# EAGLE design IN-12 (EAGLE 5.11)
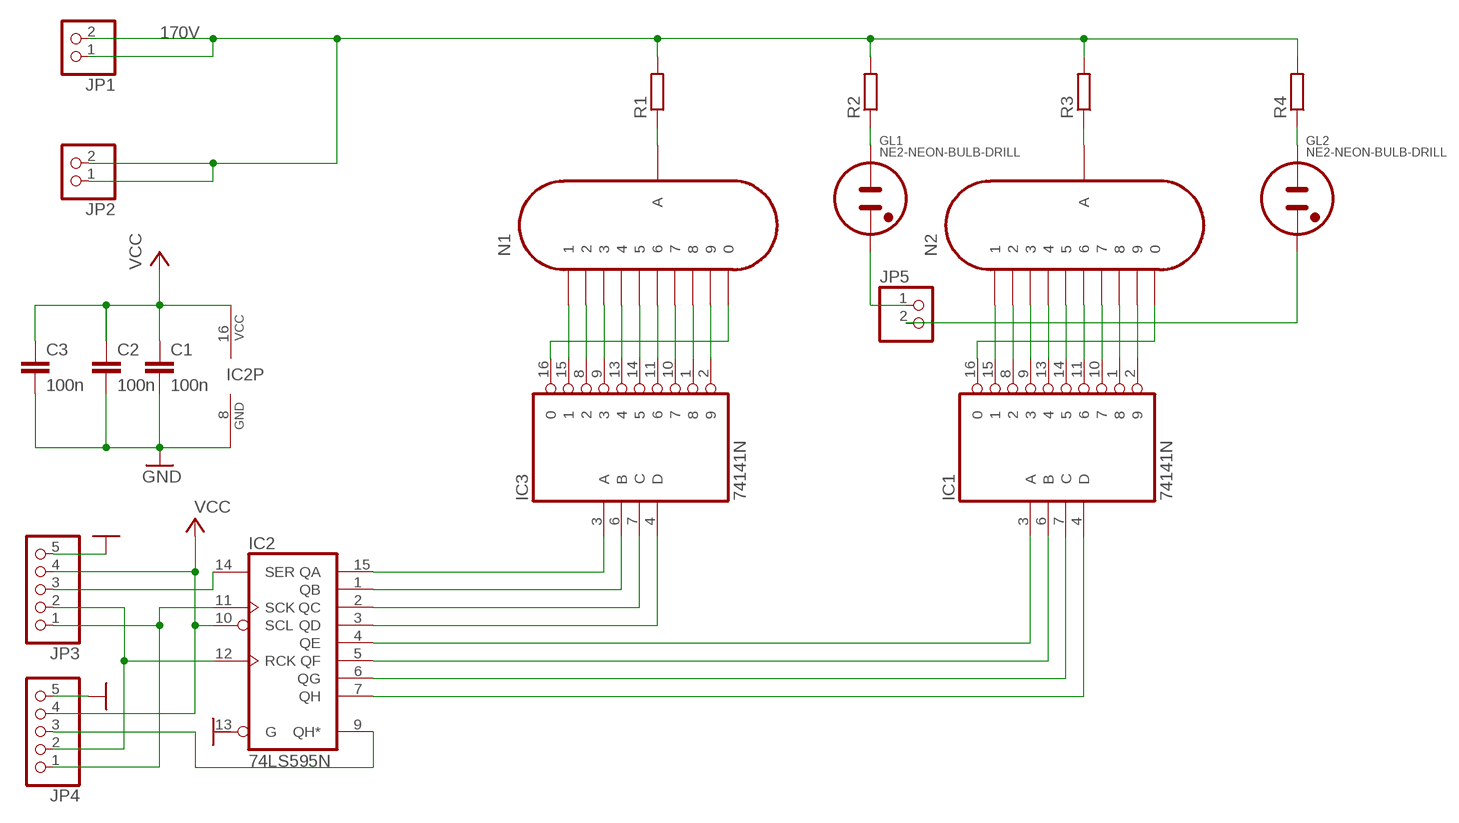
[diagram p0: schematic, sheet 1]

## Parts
C1  100n  C-EU025_050-025X075  [C025_050-025X075]
C2  100n  C-EU025_050-025X075  [C025_050-025X075]
C3  100n  C-EU025_050-025X075  [C025_050-025X075]
GL1  NE2-NEON-BULB-DRILL  [NE2-NEON-BULB-DRILL]
GL2  NE2-NEON-BULB-DRILL  [NE2-NEON-BULB-DRILL]
IC1  74141N  [DIL16]
IC2  74LS595N  [DIL16]
IC3  74141N  [DIL16]
JP1  PINHD-1X2  [1X02]
JP2  PINHD-1X2  [1X02]
JP3  PINHD-1X5  [1X05]
JP4  PINHD-1X5  [1X05]
JP5  PINHD-1X2  [1X02]
N1  IN-12A  [IN-12]
N2  IN-12A  [IN-12]
R1  R-EU_0207/12  [0207/12]
R2  R-EU_0207/12  [0207/12]
R3  R-EU_0207/12  [0207/12]
R4  R-EU_0207/12  [0207/12]

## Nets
170V: JP1.1 JP1.2 JP2.1 JP2.2 R1.2 R2.2 R3.2 R4.2
GND: C1.2 C2.2 C3.2 IC2.8(GND) IC2.13(G) JP3.5 JP4.5
N$1: N1.A R1.1
N$2: N2.A R3.1
N$3: IC1.15 N2.1
N$4: IC1.8 N2.2
N$5: IC1.9 N2.3
N$6: IC1.13 N2.4
N$7: IC1.14 N2.5
N$8: IC1.11 N2.6
N$9: IC1.10 N2.7
N$10: IC1.1 N2.8
N$11: IC1.2 N2.9
N$12: GL1.1(A) R2.1
N$13: IC3.15 N1.1
N$14: IC3.8 N1.2
N$15: IC3.9 N1.3
N$16: IC3.13 N1.4
N$17: IC3.14 N1.5
N$18: IC3.11 N1.6
N$19: IC3.10 N1.7
N$20: IC3.1 N1.8
N$21: IC3.2 N1.9
N$22: IC3.16 N1.0
N$23: IC1.16 N2.0
N$26: GL2.1(A) R4.1
N$27: GL1.2(A1) JP5.1
N$28: IC2.15(QA) IC3.3(A)
N$29: IC2.1(QB) IC3.6(B)
N$30: IC2.2(QC) IC3.7(C)
N$31: IC2.3(QD) IC3.4(D)
N$32: IC1.3(A) IC2.4(QE)
N$33: IC1.6(B) IC2.5(QF)
N$34: IC1.7(C) IC2.6(QG)
N$35: IC1.4(D) IC2.7(QH)
N$37: GL2.2(A1) JP5.2
N$40: IC2.14(SER) JP3.3
N$41: IC2.11(SCK) JP3.1 JP4.1
N$42: IC2.12(RCK) JP3.2 JP4.2
N$45: IC2.9(QH*) JP4.3
VCC: C1.1 C2.1 C3.1 IC2.10(SCL) IC2.16(VCC) JP3.4 JP4.4

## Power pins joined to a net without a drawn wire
GND: IC1.12(GND) IC3.12(GND)
VCC: IC1.5(VCC) IC3.5(VCC)

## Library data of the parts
C1-C3 = resistor:C-EU: CAPACITOR, European symbol
GL1 GL2 = nixies:NE2-NEON-BULB: Neon indicator (wire connection)
IC1 IC3 = 74xx-eu:74*141: BCD to decimal DECODER/DRIVER
IC2 = 74xx-us:74*595: 8-bit SHIFT REGISTER, output latch
JP1 JP2 JP5 = pinhead:PINHD-1X2: PIN HEADER
JP3 JP4 = pinhead:PINHD-1X5: PIN HEADER
N1 N2 = russian-nixies:IN-12A: IN-12A: medium numeric topview nixie tube
R1-R4 = resistor:R-EU_: RESISTOR, European symbol

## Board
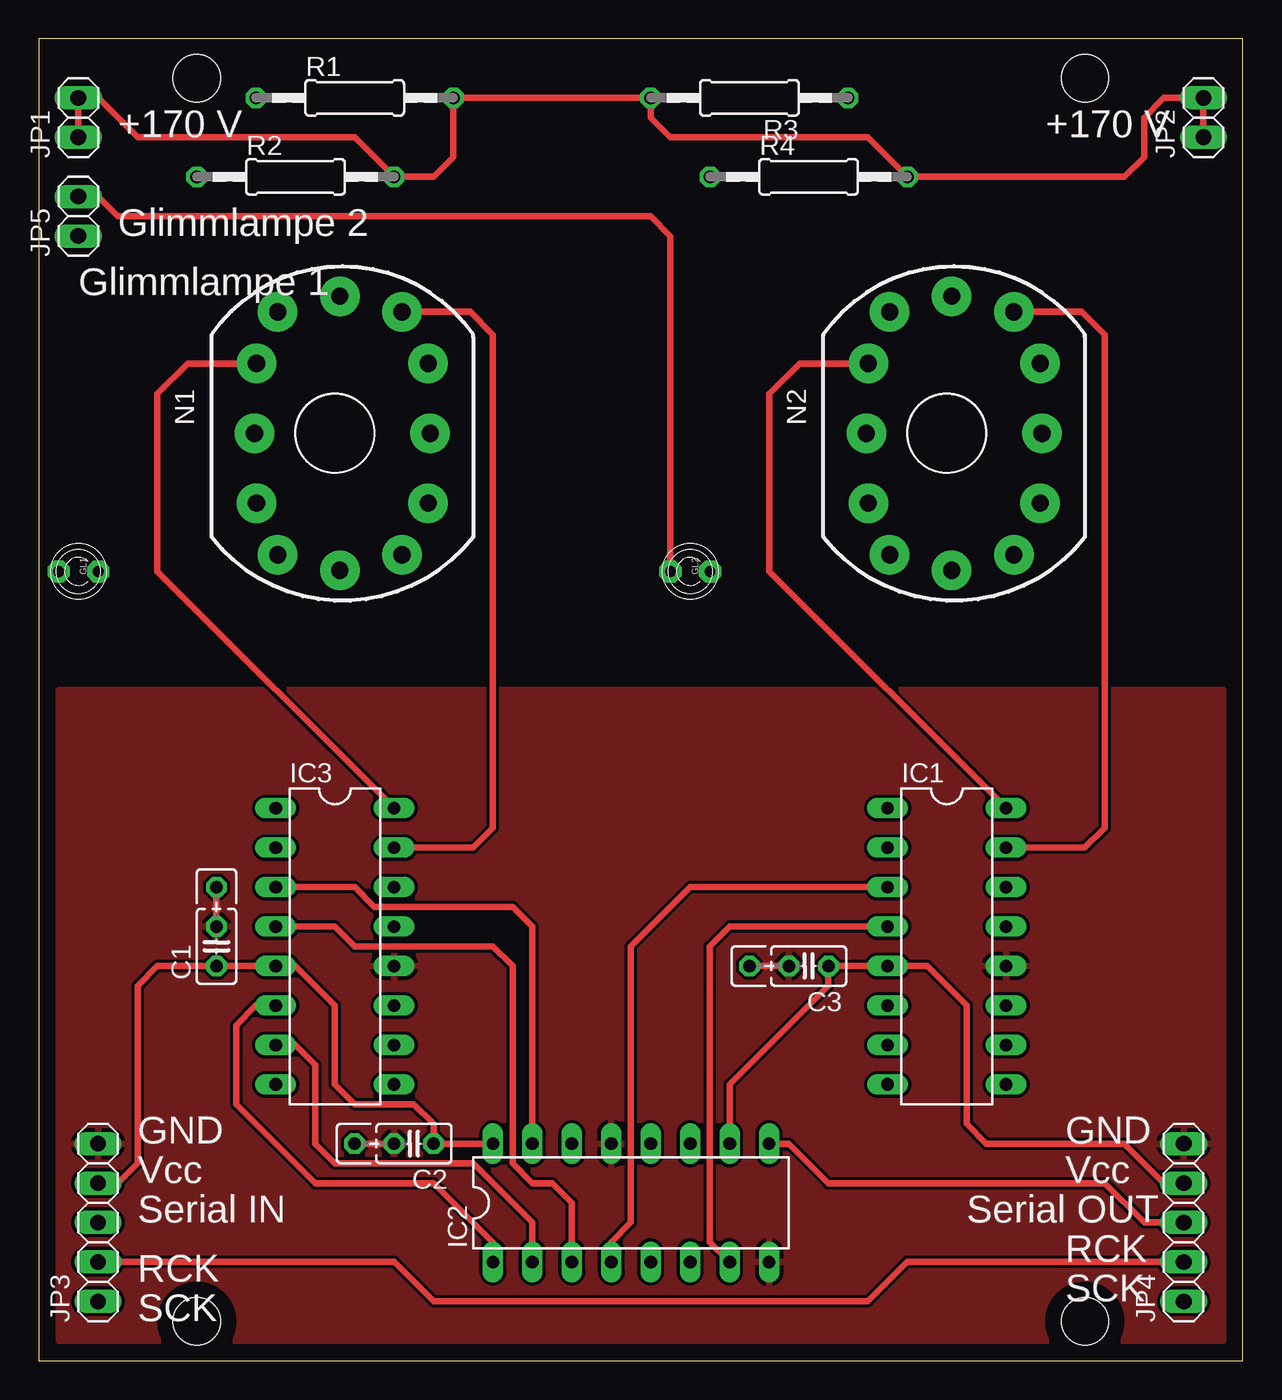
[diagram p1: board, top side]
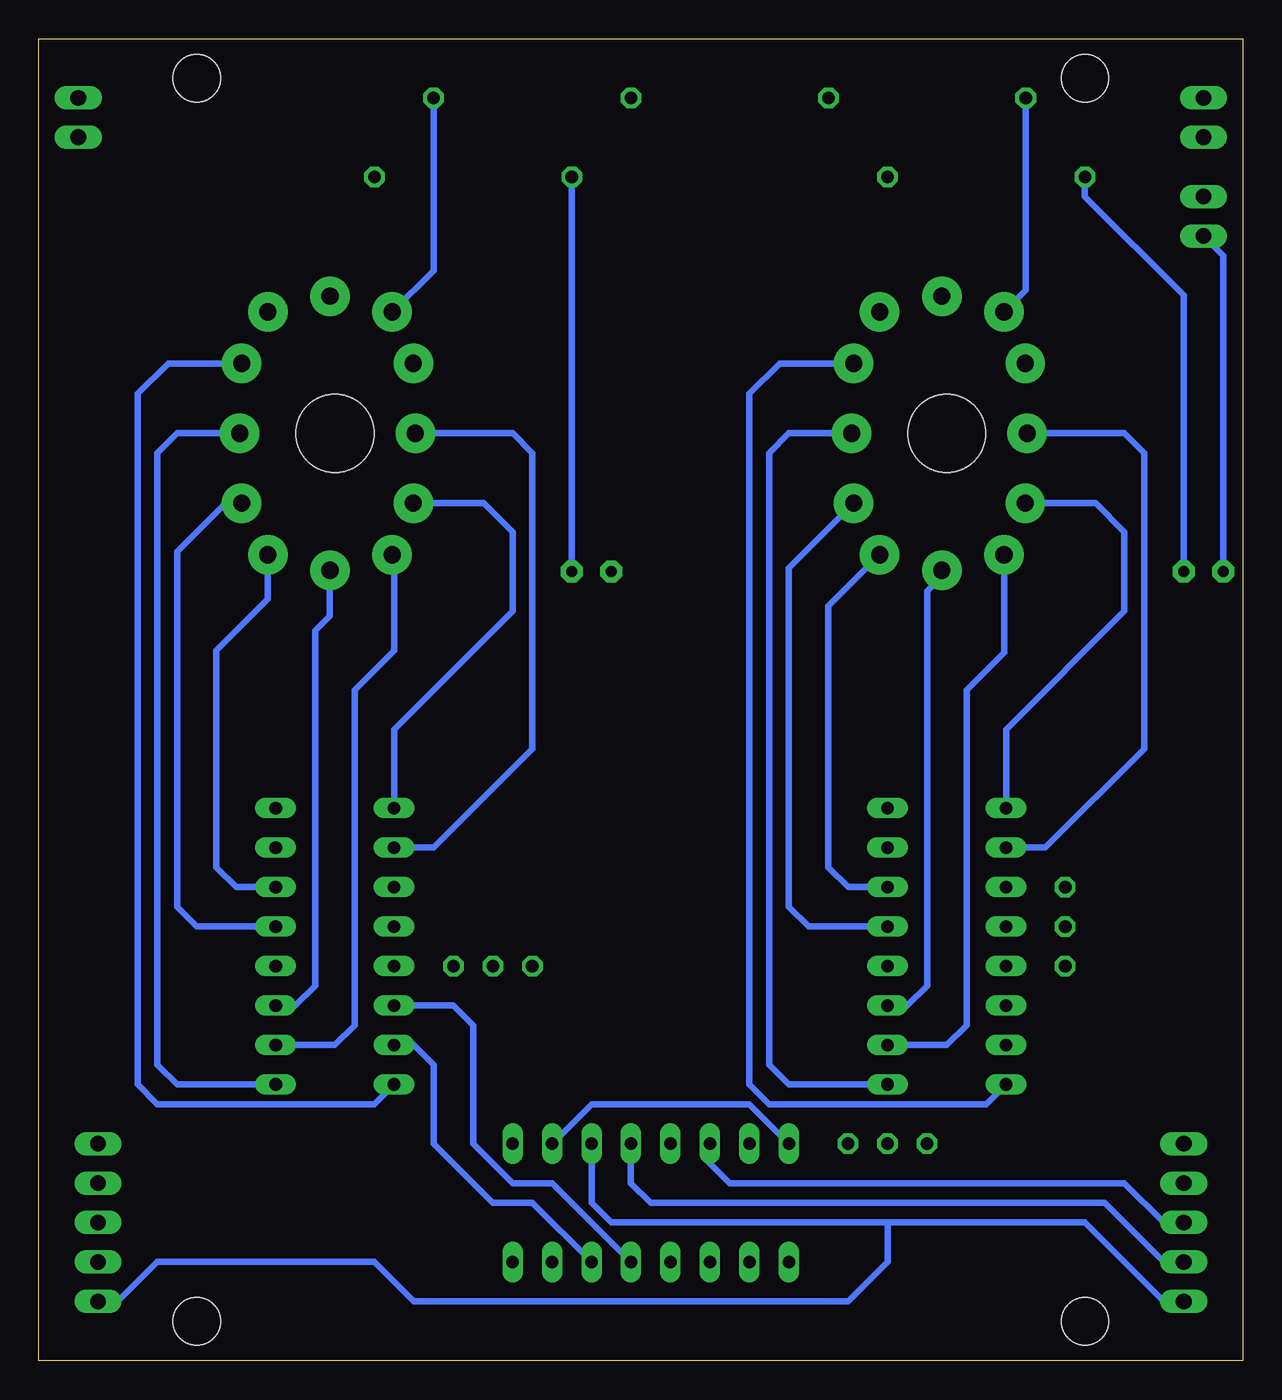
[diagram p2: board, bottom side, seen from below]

Size 77.47 x 85.08 mm. Coordinates in mm from the lower left corner, seen from the top.
Outline: 0,0 77.47,0 77.47,85.08 0,85.08 0,0
Copper layers (1*16): Top 0.035mm / dielectric 1.5mm / Bottom 0.035mm
Design rules "default": minimum track width 10mil, minimum drill 24mil, track to track 8mil, track to pad 8mil, pad to pad 8mil, via to via 8mil, smd to smd 8mil, copper to edge 40mil, drill to drill 8mil, minimum pad ring 10mil, minimum via ring 8mil, stop-mask expansion 4mil, vias tented up to drill 0mil, thermal gap 10mil
Holes 3.05 mm at 10.16,82.55 67.31,82.55 67.31,2.54 10.16,2.54

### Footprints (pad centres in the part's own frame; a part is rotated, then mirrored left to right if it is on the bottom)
C025_050-025X075 = drill 0.813 octagon: 1 -1.27,0; 2 1.27,0; 3 3.81,0
NE2-NEON-BULB-DRILL = drill 0.7 pad 1.422 octagon: 1 0,1.27; 2 0,-1.27
DIL16 = drill 0.813 long: 1 -8.89,-3.81; 2 -6.35,-3.81; 3 -3.81,-3.81; 4 -1.27,-3.81; 5 1.27,-3.81; 6 3.81,-3.81; 7 6.35,-3.81; 8 8.89,-3.81; 9 8.89,3.81; 10 6.35,3.81; 11 3.81,3.81; 12 1.27,3.81; 13 -1.27,3.81; 14 -3.81,3.81; 15 -6.35,3.81; 16 -8.89,3.81
1X02 = drill 1.016 long: 1 -1.27,0; 2 1.27,0
1X05 = drill 1.016 long: 1 -5.08,0; 2 -2.54,0; 3 0,0; 4 2.54,0; 5 5.08,0
IN-12 = drill 1.1 pad 2.54 round: 0 5.048,-4.5; 1 -4.317,-7.817; 2 -6,-4.5; 3 -6.127,0; 4 -6,4.5; 5 -4.317,7.817; 6 -0.318,8.818; 7 3.683,7.817; 8 5.048,4.5; 9 5.175,0; A 3.683,-7.817; LHDP -0.318,-8.818 | hole 5: 0,0
0207/12 = drill 0.813 octagon: 1 -6.35,0; 2 6.35,0

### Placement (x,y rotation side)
C1  11.43,26.67 90 top
C2  24.13,13.97 180 top
C3  49.53,25.4 180 top
GL1  2.54,50.8 270 top
GL2  41.91,50.8 270 top
IC1  58.42,26.67 270 top
IC2  38.1,10.16 0 top
IC3  19.05,26.67 270 top
JP1  2.54,80.01 90 top
JP2  74.93,80.01 90 top
JP3  3.81,8.89 90 top
JP4  73.66,8.89 90 top
JP5  2.54,73.66 90 top
N1  19.05,59.69 180 top
N2  58.42,59.69 180 top
R1  20.32,81.28 0 top
R2  16.51,76.2 0 top
R3  45.72,81.28 180 top
R4  49.53,76.2 0 top

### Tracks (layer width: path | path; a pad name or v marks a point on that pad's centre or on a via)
170V
  Top 0.406: JP1.1 JP1.2 3.81,81.28 6.35,78.74 20.32,78.74 R2.2 25.4,76.2 26.67,77.47 R1.2 R3.2 39.37,80.01 40.64,78.74 53.34,78.74 R4.2 69.85,76.2 71.12,77.47 71.12,80.01 72.39,81.28 JP2.2 JP2.1
GND
  Top 0.406: 20.32,13.97 C2.2 | 45.72,25.4 C3.2 | C1.2 11.43,30.48
  pour Top: 1.27,43.18 76.2,43.18 76.2,1.27 1.27,1.27
N$1
  Bottom 0.406: R1.1 13.97,68.91 N1.A
N$2
  Bottom 0.406: R3.1 52.07,70.17 N2.A
N$3
  Top 0.406: N2.1 67.11,67.51 68.58,66.04 68.58,34.29 67.31,33.02 IC1.15
N$4
  Bottom 0.406: N2.2 69.16,64.19 71.12,62.23 71.12,17.78 69.85,16.51 55.88,16.51 IC1.8
N$5
  Bottom 0.406: N2.3 68.58,59.69 69.85,58.42 69.85,19.05 68.58,17.78 IC1.9
N$6
  Bottom 0.406: N2.4 65.46,55.19 68.58,52.07 68.58,29.21 67.31,27.94 IC1.13
N$7
  Bottom 0.406: N2.5 62.74,49.02 66.04,45.72 66.04,31.75 64.77,30.48 IC1.14
N$8
  Bottom 0.406: N2.6 58.74,47.94 59.69,46.99 59.69,24.13 60.96,22.86 IC1.11
N$9
  Bottom 0.406: IC1.10 58.42,20.32 57.15,21.59 57.15,43.18 54.61,45.72 54.61,51.74 N2.7
N$10
  Bottom 0.406: N2.8 48.84,55.19 46.99,53.34 46.99,48.26 54.61,40.64 IC1.1
N$11
  Bottom 0.406: N2.9 46.99,59.69 45.72,58.42 45.72,39.37 52.07,33.02 IC1.2
N$12
  Bottom 0.406: R2.1 10.16,74.93 3.81,68.58 GL1.1
N$13
  Top 0.406: N1.1 27.74,67.51 29.21,66.04 29.21,34.29 27.94,33.02 IC3.15
N$14
  Bottom 0.406: IC3.8 16.51,16.51 30.48,16.51 31.75,17.78 31.75,62.23 29.79,64.19 N1.2
N$15
  Bottom 0.406: IC3.9 29.21,17.78 30.48,19.05 30.48,58.42 29.21,59.69 N1.3
N$16
  Bottom 0.406: IC3.13 27.94,27.94 29.21,29.21 29.21,51.03 N1.4
N$17
  Bottom 0.406: IC3.14 25.4,30.48 26.67,31.75 26.67,48.57 N1.5
N$18
  Bottom 0.406: IC3.11 21.59,22.86 20.32,24.13 20.32,49.53 19.37,50.48 N1.6
N$19
  Bottom 0.406: IC3.10 19.05,20.32 17.78,21.59 17.78,43.18 15.37,45.59 N1.7
N$20
  Bottom 0.406: IC3.1 15.24,40.64 7.62,48.26 7.62,53.34 9.47,55.19 N1.8
N$21
  Bottom 0.406: IC3.2 12.7,33.02 6.35,39.37 6.35,58.42 7.62,59.69 N1.9
N$22
  Top 0.406: IC3.16 7.62,50.8 7.62,62.23 9.58,64.19 N1.0
N$23
  Top 0.406: IC1.16 46.99,50.8 46.99,62.23 48.95,64.19 N2.0
N$26
  Bottom 0.406: GL2.1 R4.1
N$27
  Bottom 0.406: GL1.2 1.27,71.12 JP5.1
N$28
  Top 0.406: IC2.15 31.75,27.94 30.48,29.21 21.59,29.21 20.32,30.48 IC3.3
N$29
  Top 0.406: IC2.1 29.21,7.62 25.4,11.43 17.78,11.43 12.7,16.51 12.7,21.59 13.97,22.86 IC3.6
N$30
  Top 0.406: IC2.2 31.75,8.89 27.94,12.7 19.05,12.7 17.78,13.97 17.78,19.05 16.51,20.32 IC3.7
N$31
  Top 0.406: IC3.4 19.05,27.94 20.32,26.67 29.21,26.67 30.48,25.4 30.48,12.7 31.75,11.43 33.02,11.43 34.29,10.16 IC2.3
N$32
  Top 0.406: IC2.4 36.83,7.62 38.1,8.89 38.1,26.67 41.91,30.48 IC1.3
N$33
  Bottom 0.406: IC2.5 44.45,11.43 46.99,11.43 49.53,13.97 49.53,21.59 50.8,22.86 IC1.6
N$34
  Bottom 0.406: IC2.6 45.72,10.16 48.26,10.16 52.07,13.97 52.07,19.05 53.34,20.32 IC1.7
N$35
  Top 0.406: IC1.4 44.45,27.94 43.18,26.67 43.18,7.62 IC2.7
N$37
  Top 0.406: JP5.2 3.81,74.93 5.08,73.66 39.37,73.66 40.64,72.39 GL2.2
N$40
  Bottom 0.406: JP3.3 5.08,8.89 7.62,11.43 33.02,11.43 34.29,12.7 IC2.14
N$41
  Bottom 0.406: JP3.1 5.08,3.81 10.16,8.89 22.86,8.89 | 22.86,8.89 40.64,8.89 41.91,10.16 IC2.11 | JP4.1 72.39,3.81 69.85,6.35 55.88,6.35 53.34,3.81 25.4,3.81 22.86,6.35 22.86,8.89
N$42
  Top 0.406: 72.39,6.35 JP4.2 55.88,6.35 53.34,3.81 25.4,3.81 22.86,6.35 JP3.2
  Bottom 0.406: JP3.2 5.08,6.35 8.89,10.16 38.1,10.16 39.37,11.43 IC2.12
N$45
  Top 0.406: IC2.9 48.26,13.97 50.8,11.43 68.58,11.43 71.12,8.89 JP4.3
VCC
  Top 0.406: JP3.4 5.08,11.43 6.35,12.7 6.35,24.13 7.62,25.4 C1.1 IC3.5 16.51,25.4 19.05,22.86 19.05,17.78 20.32,16.51 24.13,16.51 25.4,15.24 C2.1 IC2.16 | IC2.10 44.45,17.78 50.8,24.13 C3.1 IC1.5 57.15,25.4 59.69,22.86 59.69,15.24 60.96,13.97 69.85,13.97 72.39,11.43 JP4.4
  Bottom 0.406: IC2.16 31.75,16.51 41.91,16.51 IC2.10

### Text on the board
tPlace: +170 V | +170 V | Glimmlampe 2 | Glimmlampe 1 | GND | GND | Vcc | Vcc | Serial IN | Serial OUT | RCK | RCK | SCK | SCK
